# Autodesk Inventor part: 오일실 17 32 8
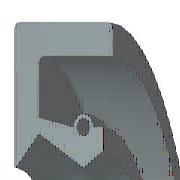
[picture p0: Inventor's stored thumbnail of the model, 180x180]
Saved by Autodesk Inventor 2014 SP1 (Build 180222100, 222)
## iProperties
Created: 2012-02
Part Number: 오일실 17 32 8
Material: 고무
Description: 오일-실
Document SubType Name: Modeling
Standard: KS B 2804
Designer: mduedu
Standards Organization: KS
Language: ko-KR
Size Designation: D - 17 32 8
Categories: <MemberInstance><Categories><Category DisplayName="샤프트 부품" InternalName="7f7aeb1f-a693-4053-b835-cee3144e0d98" Mnemonic="SHFT"><Category DisplayName="실링" Intern
Density: 0.93 g/cm^3
Appearance: 고무 - 검은색 - 버전 1.1
IsCustomPart: 1
Author: mduedu
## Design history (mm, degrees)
revolve "본체" stored, may be unused: angle "d17" = 90 deg
revolve "스프링1" stored, may be unused: angle "d18" = 90 deg
body "Solid1"
sketch "스케치1"
  geometry: L1 (0, 16)-(8, 16); L2 (8, 14.25)-(1.75, 14.25); L3 (1.75, 10.25)-(4.9, 8.5); L4 (4.9, 8.5)-(0, 8.5); L5 (0, 0)-(9.586, 0) reference; L6 (4.9, 8.5)-(6.3, 9.375); L7 (0, 18)-(0, -3) reference; L8 (-1.941, 0)-(11.507, 0) reference; L9 (4.2, 10.6)-(1.75, 11.21); L10 (1.75, 11.21)-(1.75, 14.25); L11 (0, 16)-(0, 8.588); L12 (4.9, 8.5)-(0, 8.5); L13 (1.75, 10.25)-(0.152, 8.528); L14 (8, 16)-(8, 14.25); L15 (5.6, 10.6)-(6.3, 10.6); L16 (6.3, 10.6)-(6.3, 9.375); C1 r 0.455 at (4.9, 10.6); A1 r 0.7 centre (4.9, 10.6) between (5.6, 10.6) and (4.2, 10.6); A2 r 0.088 centre (0.088, 8.588) between (0, 8.588) and (0.152, 8.528); 1 further point
  constraints: 28 end point, 5 horizontal alignment, 5 point on line, 4 point on circle, 4 vertical alignment, 3 centre point, 3 tangent, 2 collinear, 2 horizontal, 2 perpendicular, 1 coincident, 1 parallel
  dimensions: "d0" = 32 diameter of L1 L5 (= SD2); "d1" = 1.75 distance of L1.end L2.start (= SD); "d2" = 0.91 diameter of C1 (= SPDI); "d3" = 1.4 diameter of A1 (= SPDA); "d4" = 17 diameter of L3.end L5 (= NND); "d5" = 20.5 diameter of L3.start L5 (= TKDM); "d7" = 22.42 diameter of L9.end L5 (= TKDM + 0.24 x SWDT); "d8" = 1.75 distance between parallel lines of L11 L10 (= SD); "d9" = 4.9 distance from line of L11 C1.centre (= SPDST); "d10" = 21.2 diameter of C1.centre L5 (= HLDM); "d11" = 0.0875 radius of A2 (= 0.25 x LAB); "d12" = 6.3 distance between parallel lines of L11 L16 (= SDI); "d13" = 18.75 diameter of L6.end L5 (= ABDM); "d14" = 8 distance from line of L11 L1.end (= SWDT)
fillet "모깎기1" dims "d6" = 0.3 (= RR)
other parameters: "SD2" = 32 [user parameter; used in 1 equation term], "SWDT" = 8 [user parameter; used in 2 equation terms], "RR" = 0.3 [user parameter; used in 1 equation term], "SD" = 1.75 [user parameter; used in 2 equation terms], "NND" = 17 [user parameter; used in 1 equation term], "SPDA" = 1.4 [user parameter; used in 1 equation term], "SPDI" = 0.91 [user parameter; used in 1 equation term], "TKDM" = 20.5 [user parameter; used in 2 equation terms], "HLDM" = 21.2 [user parameter; used in 1 equation term], "ABDM" = 18.75 [user parameter; used in 1 equation term], "SDI" = 6.3 [user parameter; used in 1 equation term], "SPDST" = 4.9 [user parameter; used in 1 equation term], "LAB" = 0.35 [user parameter; used in 1 equation term], "d15" = 0, "d16" = 0, "d19" = 0
